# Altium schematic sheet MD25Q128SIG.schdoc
size 127 x 101 mm
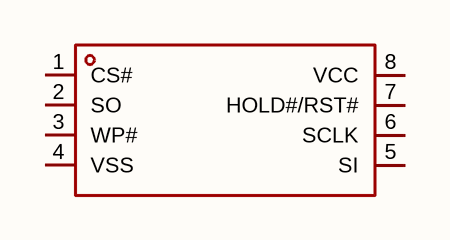
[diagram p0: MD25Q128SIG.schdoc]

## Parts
U?  md25q128sig  [SOIC-8_L5.3-W5.3-P1.27-LS7.9-BL]  (value not drawn)

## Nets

Not connected (* = marked no-connect by the designer): U? 1(CS#) 2(SO) 3(WP#) 4(VSS) 5(SI) 6(SCLK) 7(HOLD#/RST#) 8(VCC)

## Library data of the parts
U? = md25q128sig: 接口类型:SPI;存储容量:128Mbit;时钟频率(fc):104MHz;; Manufacturer: GigaDevice(兆易创新); AddInBom: yes; ModelId: 78e311bc6cdb4f2a8ea91f8efea56c7d; ModelTransform: 311.023,207.8736,0,90,0,0,0,0,0; Interface: SPI; Clock Frequency: 104MHz; Voltage - Supply: 2.7V~3.6V; Standby Supply Current: 5uA; Program / Erase Cycles: 100000次; Page Programming Time (Tpp): 600us; Block Erase Time(tBE): 200ms@(32KB); Data Retention - TDR (Year): 20年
